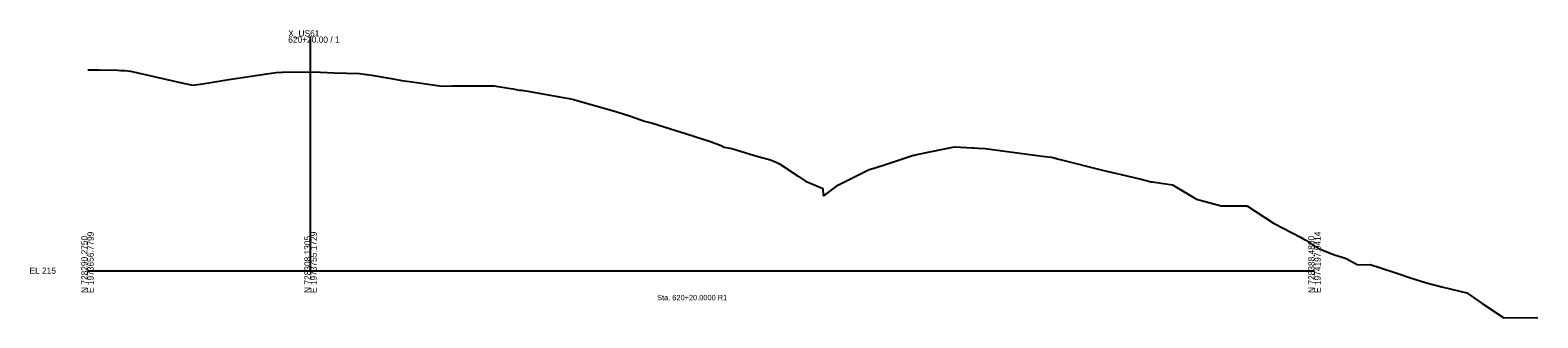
# Model space of a CAD drawing. Extents: x -26 to 1629, y -25 to 9635.
# Drawn here: x -26 to 650, y 479 to 608 of the extents above; entities that cross this region are included whole.
import ezdxf

# ---------------------------------------------------------------- set-up
doc = ezdxf.new("R2010")
doc.units = 0
for name, color, linetype in [('Draft_XS_Grid', 7, 'Continuous'), ('Draft_XS_Text', 7, 'Continuous'), ('DTM_X_GROUND', 7, 'Continuous'), ('XS_CELL', 7, 'Continuous')]:
    doc.layers.add(name, color=color, linetype=linetype)

msp = doc.modelspace()

# ---------------------------------------------------------------- linework, layer by layer
at = {"layer": 'DTM_X_GROUND'}
msp.add_lwpolyline([(0.13, 590.12), (5.28, 590.05), (13.47, 589.94), (15, 589.82), (16.79, 589.68), (19.29, 589.38), (42.92, 584.03), (47.23, 583.1), (52.65, 583.97), (63.31, 585.64), (80.34, 588.2), (84.56, 588.83), (87.12, 588.98), (87.22, 588.98), (87.62, 588.99), (101.16, 589.09), (110.51, 588.77), (122, 588.37), (124.9, 588.03), (125.41, 587.97), (127.28, 587.64), (136.15, 586.11), (140.94, 585.29), (147.65, 584.35), (158.78, 582.69), (163.26, 582.88), (182.24, 582.87), (189.69, 581.71), (190.81, 581.55), (193.58, 580.98), (194.71, 580.89), (197.36, 580.51), (203.28, 579.43), (213.21, 577.7), (215.86, 577.16), (217.86, 576.68), (236.82, 571.44), (243.38, 569.27), (249.74, 566.98), (253.24, 566.11), (271.39, 560.46), (273.09, 559.87), (278.88, 558), (284.11, 556.1), (285.39, 555.41), (288.87, 554.77), (299.02, 551.71), (306.2, 549.7), (308.67, 548.6), (309.07, 548.46), (310.17, 547.84), (318.51, 542.39), (321.91, 540.09), (328.22, 537.42), (329.63, 536.82), (329.81, 533.84), (330.08, 533.6), (336.64, 538.51), (350.45, 545.33), (353.03, 546.11), (354.93, 546.68), (356.75, 547.34), (370.26, 551.73), (370.4, 551.76), (370.71, 551.82), (371.76, 552.04), (384.15, 554.62), (388.69, 555.56), (396.7, 555.05), (397.34, 555.02), (399.29, 554.9), (402.32, 554.74), (427.87, 551.37), (431.97, 550.84), (432.74, 550.71), (435.44, 550.01), (455.57, 544.91), (459.5, 544.09), (471.79, 541.17), (476.86, 539.85), (477.45, 539.83), (478.36, 539.74), (486.36, 538.44), (497.12, 532.03), (500.99, 531), (508.14, 529.05), (519.67, 529.02), (519.74, 529), (519.92, 528.9), (531.66, 521.3), (539.98, 516.95), (543.76, 515.02), (545.26, 514.16), (546.11, 513.66), (551.45, 510.11), (558.57, 507.32), (562.91, 505.85), (564.22, 505.41), (569.21, 502.8), (571.97, 502.67), (574.91, 502.77), (579.53, 501.2), (586.87, 498.9), (593.03, 496.8), (600.23, 494.48), (607.09, 492.73), (615.75, 490.69), (618.34, 490.06), (625.15, 485.24), (634.88, 478.85), (650.13, 479.01)], dxfattribs=at)
at = {"layer": 'XS_CELL'}
for p, q in [((100, 500), (100, 605)), ((0, 500), (100, 500)), ((100, 500), (550, 500))]:
    msp.add_line(p, q, dxfattribs=at)

# ---------------------------------------------------------------- texts
at = {"layer": 'Draft_XS_Grid'}
msp.add_text('-', height=0.0001, dxfattribs=at).set_placement((0, 500))
at = {"layer": 'Draft_XS_Text'}
msp.add_text('Sta. 620+20.0000 R1', height=2.4, dxfattribs=at).set_placement((255.34, 486.75))
at = {"layer": 'XS_CELL'}
for s, p in [('X_US61', (90, 605)), ('620+20.00 / 1', (90, 602.2)), ('EL 215', (-26, 498.6))]:
    msp.add_text(s, height=2.8, dxfattribs=at).set_placement(p)
for s, p in [('N 728290.2750', (0, 490)), ('E 1973656.7799', (2.8, 490)), ('N 728308.1305', (100, 490)), ('E 1973755.1729', (102.8, 490)), ('N 728388.4800', (550, 490)), ('E 1974197.9414', (552.8, 490))]:
    msp.add_text(s, height=2.8, rotation=90, dxfattribs=at).set_placement(p)

doc.saveas('drawing.dxf')
